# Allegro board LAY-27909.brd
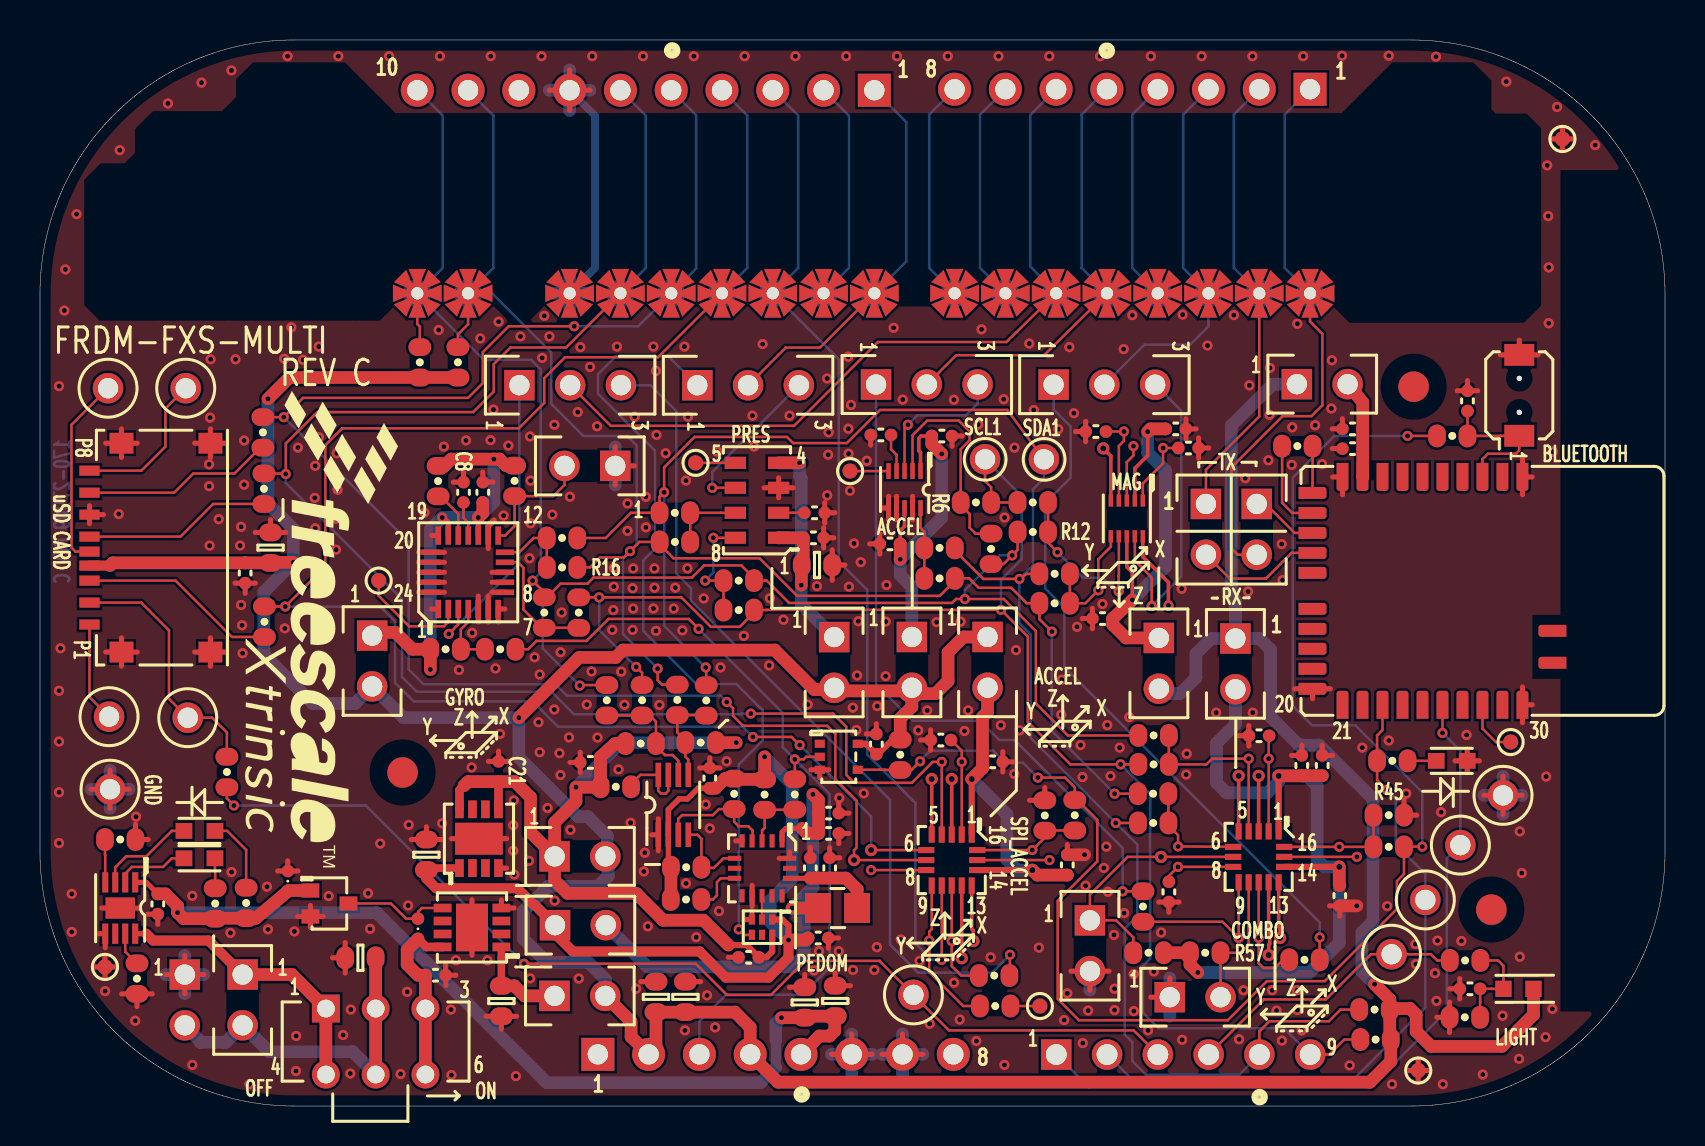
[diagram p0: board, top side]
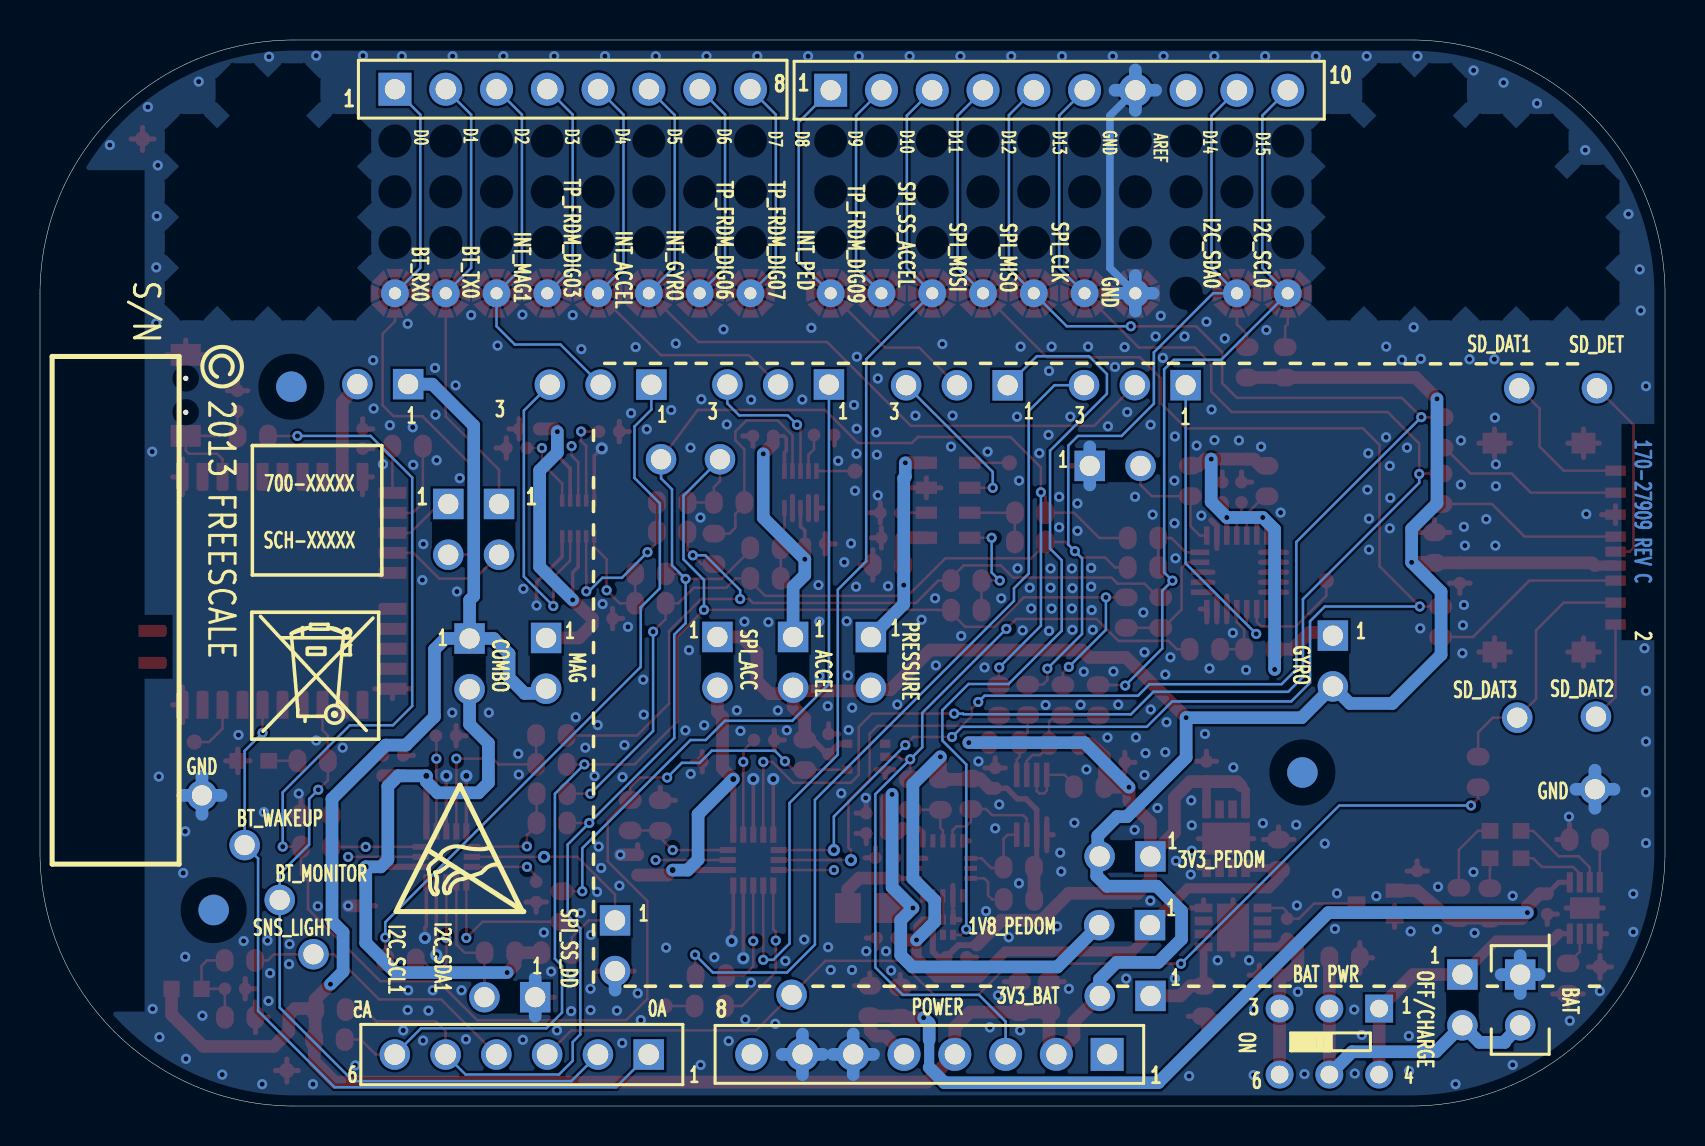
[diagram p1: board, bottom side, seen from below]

Outline 81.28 x 53.34 mm; copper layers: TOP, BOTTOM. Coordinates in mm from the lower left corner of the outline.
Outline path: 0,40.64 0,12.7 arc(3.74,3.72) 12.73,0 68.58,0 arc(77.56,3.72) 81.28,12.7 81.28,40.64 arc(77.56,49.62) 68.58,53.34 12.73,53.34 arc(3.73,49.63) 0,40.64

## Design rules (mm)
net group POW: nets P3V3
net group POWER_SPACE: nets P1V8 P1V8_MMA9553L_VDDA P1V8_PED P3V3_ACCEL P3V3_BT P3V3_COMBO P3V3_GYRO P3V3_MAG P3V3_PEDOM P3V3_PRESSURE P3V3_SPI_ACC P3V3_VBAT P3V7_BAT P4V2_BAT P4V2_BAT_OUT P5-9V_VOUT P5V_USB
nets with their own width: min track width 0.635; nets GND

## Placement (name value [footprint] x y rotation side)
C1  4.7uF  [CC0402_25]  65.65 33.88 180 top
C2  0.1UF  [CC0402_25]  56.81 33.88 0 top
C3  0.1UF  [CC0402_25]  65.65 32.89 180 top
C4  1.0UF  [CC0402_25]  45.11 33.52 0 top
C5  0.1UF  [CC0402_25]  42.06 33.58 180 top
C6  0.1UF  [CC0402_25]  52.81 33.75 180 top
C7  0.1UF  [CC0402_25]  57.44 32.92 0 top
C8  0.1UF  [CC0402_25]  21.18 30.71 90 top
C9  1.0UF  [CC0402_25]  22.15 30.71 90 top
C10  0.1UF  [CC0402_25]  38.74 29.68 0 top
C11  10uF  [CC0603_OV]  11.53 27.94 90 top
C12  0.1UF  [CC0402_25]  38.69 28.43 0 top
C13  0.1UF  [CC0402_25]  10.26 26.67 270 top
C14  10uF  [CC0603_OV]  38.86 27.07 0 top
C15  0.1UF  [CC0402_25]  42.51 28.13 180 top
C16  1.0UF  [CC0402_25]  53.15 24.39 180 top
C17  0.1UF  [CC0402_25]  45.06 18.31 180 top
C18  0.1UF  [CC0402_25]  60.97 18.53 180 top
C19  4.7uF  [CC0402_25]  63.11 17.04 90 top
C20  0.1UF  [CC0402_25]  64.14 17.04 90 top
C21  1.0UF  [CC0402_25]  22.94 16.74 90 top
C22  1.0UF  [CC0402_25]  47.65 17.22 0 top
C23  0.1UF  [CC0402_25]  27.53 17.19 180 top
C24  0.1UF  [CC0402_25]  33.5 16.41 90 top
C25  1.0UF  [CC0402_25]  39.45 14.66 0 top
C26  0.1UF  [CC0402_25]  39.45 13.64 0 top
C27  10uF  [CC0603_OV]  19.33 12.57 90 top
C28  0.1UF  [CC0402_25]  51.38 12.07 90 top
C29  0.1UF  [CC0402_25]  38.53 11.91 90 top
C30  1.0UF  [CC0402_25]  39.5 11.91 90 top
C31  0.1UF  [CC0402_25]  56.46 10.71 270 top
C32  0.1UF  [CC0402_25]  65.01 10.52 270 top
C33  0.1UF  [CC0402_25]  38.93 8.41 0 top
C34  1.0UF  [CC0402_25]  5.89 10.11 270 top
C35  10uF  [CC0603_OV]  16.03 7.42 180 top
C36  0.1UF  [CC0402_25]  35.45 7.44 180 top
C37  1.0UF  [CC0402_25]  19.78 6.55 0 top
C38  10uF  [CC0603_OV]  23.08 5.25 270 top
C39  0.1UF  [CC0402_25]  71.52 5.86 180 top
C40  2.2UF  [CC0603_OV]  30.81 5.46 90 top
C41  10uF  [CC0603_OV]  32.28 5.46 90 top
C42  10uF  [CC0603_OV]  39.78 5.26 90 top
C43  2.2UF  [CC0603_OV]  38.25 5.18 90 top
C44  1.0UF  [CC0402_25]  41.83 18.11 90 top
C46  0.1UF  [CC0402_25]  71.4 35.28 90 top
D1  BLUE  [LED_0603]  70.61 17.27 0 top
D2  LED GREEN  [LED_0603]  7.98 13.77 180 top
D3  LED ORANGE  [LED_0603]  7.98 12.4 180 top
J1  SKT_1X8  [CON_SKT1X8_TH]  63.53 50.88 90 bottom
J2  SKT_1X10  [CON_SKT1X10_TH]  41.73 50.83 90 bottom
J3  HDR TH 1X3  [HDR103]  50.7 36.09 90 top
J4  HDR TH 1X3  [HDR103]  41.82 36.1 90 top
J5  HDR TH 1X3  [HDR103]  32.88 36.06 90 top
J6  HDR TH 1X3  [HDR103]  23.98 36.07 90 top
J7  HDR 1X2 TH  [HDR102]  62.87 36.12 90 top
J8  HDR 1X2 TH  [SH_HDR102_BOTTOM]  28.77 32.03 270 top
J9  SKT_1X8  [CON_SKT1X8_TH]  27.9 2.58 270 bottom
J10  SKT_1X6  [CON_SKT1X6_TH]  50.83 2.58 270 bottom
J11  CON microSD  [CON8_SDCARD_PUSH_SM]  6.4 27.94 270 top
J12  HDR 1X2 TH  [SH_HDR102_BOTTOM]  55.96 23.42 0 top
J13  HDR 1X2 TH  [SH_HDR102_BOTTOM]  43.61 23.47 0 top
J14  HDR 1X2 TH  [SH_HDR102_BOTTOM]  39.72 23.46 0 top
J15  HDR 1X2 TH  [SH_HDR102_BOTTOM]  16.61 23.54 0 top
J16  HDR 1X2 TH  [SH_HDR102_BOTTOM]  59.79 23.39 0 top
J17  HDR 1X2 TH  [SH_HDR102_BOTTOM]  47.4 23.47 0 top
J18  HDR 1X2 TH  [SH_HDR102_BOTTOM]  25.74 12.49 90 top
J19  HDR 1X2 TH  [SH_HDR102_BOTTOM]  10.13 6.58 0 top
J20  HDR 1X2 TH  [SH_HDR102_BOTTOM]  25.76 9.05 90 top
J21  HDR 1X2 TH  [SH_HDR102_BOTTOM]  52.52 9.29 0 top
J22  HDR 1X2 TH  [HDR102]  25.73 5.51 90 top
J23  HDR 1X2 TH  [SH_HDR102_BOTTOM]  56.51 5.45 90 top
J24  HDR 1X2 TH  [HDR102]  7.24 6.58 180 bottom
J25  HDR 1X2 TH  [SH_HDR102_BOTTOM]  60.86 30.12 0 top
J26  HDR 1X2 TH  [SH_HDR102_BOTTOM]  58.32 30.12 0 top
L1  330 OHM  [IND_0805]  39.89 9.91 180 top
NOREF  -  []  59.45 10.97 90 top
NOREF#2  -  []  44.33 12.81 90 top
NOREF#3  -  []  44.6 11.03 0 top
NOREF#4  -  []  70.32 0.01 90 top
NOREF#5  -  []  -16.59 -36.7 0 top
NOREF#6  -  []  14.31 2.92 0 top
NOREF#7  -  []  10.29 35.81 270 top
NOREF#8  -  []  44.6 11.03 0 top
NOREF#9  -  []  8.69 5.03 0 top
NOREF#10  -  []  -381.97 185.27 0 top
NOREF#11  -  [unnamed#2]  68.71 35.99 0 top
NOREF#12  -  []  59.95 11.19 90 top
NOREF#13  -  []  59.45 10.97 0 top
NOREF#14  -  []  -32.92 -145.92 0 top
NOREF#15  -  []  7.24 6.58 0 top
NOREF#16  -  []  44.33 11.81 0 top
NOREF#17  -  []  62.45 10.98 0 top
NOREF#18  -  []  44.6 11.03 90 top
NOREF#19  -  []  27.17 40.56 0 top
NOREF#20  -  [unnamed#2]  18.14 16.69 0 top
NOREF#21  -  []  44.33 12.31 90 top
NOREF#22  -  []  59.95 11.19 0 top
NOREF#23  -  []  78.12 49.02 0 top
NOREF#24  -  []  59.68 11.97 0 top
NOREF#25  -  []  192.91 64.47 0 top
NOREF#26  -  []  47.1 10.82 0 top
NOREF#27  -  []  59.95 11.19 0 top
NOREF#28  -  []  17.63 46.92 0 top
NOREF#29  -  []  14.3 1.57 90 top
NOREF#30  -  []  14.31 1.42 90 top
NOREF#31  -  []  59.95 11.19 0 top
NOREF#32  -  []  44.1 10.81 90 top
NOREF#33  -  []  8.69 -3.96 90 top
NOREF#34  -  [unnamed#2]  72.59 9.83 0 top
NOREF#35  -  []  7.16 3.38 0 top
NOREF#36  -  []  14.3 1.57 0 top
NOREF#37  -  []  43.62 50.09 0 top
NOREF#38  -  []  44.1 10.81 0 top
NOREF#39  -  []  59.68 12.97 90 top
NOREF#40  -  []  -408 -339.88 0 top
NOREF#41  -  []  0 41.47 0 top
NOREF#42  -  []  44.6 11.03 0 top
NOREF#43  -  []  7.24 4.04 0 top
NOREF#44  -  []  64.74 46.67 0 top
NOREF#45  -  []  -28.19 6.65 0 top
NOREF#46  -  []  59.68 12.47 90 top
NOREF#47  -  []  55.29 -16.24 180 bottom
NOREF#48  -  []  91.82 39.52 180 bottom
NOREF#49  -  []  54.66 12.88 180 bottom
NOREF#50  -  []  54.61 5.51 180 bottom
NOREF#51  -  []  2.8 32.76 270 bottom
NOREF#52  -  [unnamed#2]  68.71 35.99 180 bottom
NOREF#53  -  [unnamed#2]  72.59 9.8 180 bottom
NOREF#54  -  [unnamed#2]  18.14 16.69 180 bottom
NOREF#55  -  []  8.16 33.42 270 bottom
NOREF#56  -  []  25.11 -7.83 180 bottom
NOREF#57  -  []  41.72 -15.38 180 bottom
Q1  NTS4001NT1G  [SC70_3]  14.48 10.13 270 top
Q2  ALS-PT19-315C/L177/TR8  [PHTRANS_1P9X1]  73.95 5.86 180 top
R1  0  [RC0603_OV]  9.35 16.71 90 top
R2  0  [RC0603_OV]  70.64 33.53 180 top
R3  0  [RC0603_OV]  11.15 33.71 270 top
R4  10K  [RC0603_OV]  19.91 31.27 270 top
R5  10K  [RC0603_OV]  23.74 31.28 270 top
R6  0  [RC0603_OV]  46.81 30.2 0 top
R7  0  [RC0603_OV]  49.66 30.2 180 top
R8  0  [RC0603_OV]  62.89 33.02 0 top
R9  0  [RC0603_OV]  11.2 30.89 270 top
R10  0  [RC0603_OV]  31.75 29.68 180 top
R11  0  [RC0603_OV]  47.57 27.88 270 top
R12  0  [RC0603_OV]  49.66 28.72 180 top
R13  0  [RC0603_OV]  26.11 28.42 0 top
R14  0  [RC0603_OV]  31.76 28.22 180 top
R16  0  [RC0603_OV]  26.11 26.95 0 top
R18  0  [RC0603_OV]  50.75 26.63 180 top
R19  0  [RC0603_OV]  50.75 25.16 180 top
R20  0  [RC0603_OV]  44.99 26.4 0 top
R21  0  [RC0603_OV]  44.99 27.93 0 top
R22  0  [RC0603_OV]  11.23 24.23 270 top
R23  0  [RC0603_OV]  34.95 24.82 0 top
R24  0  [RC0603_OV]  34.95 26.29 0 top
R25  0  [RC0603_OV]  25.22 24.69 90 top
R26  0  [RC0603_OV]  26.95 24.69 90 top
R27  10K  [RC0603_OV]  20.29 22.85 0 top
R28  0  [RC0603_OV]  23.02 22.85 0 top
R29  0  [RC0603_OV]  28.35 20.3 90 top
R30  0  [RC0603_OV]  30.12 20.3 90 top
R31  0  [RC0603_OV]  33.32 20.29 90 top
R32  0  [RC0603_OV]  31.88 20.32 90 top
R33  0  [RC0603_OV]  55.7 17.09 180 top
R34  0  [RC0603_OV]  55.7 18.54 180 top
R35  10K  [RC0603_OV]  43.03 17.58 270 top
R36  4.7K  [RC0603_OV]  30.05 18.14 0 top
R37  4.7K  [RC0603_OV]  33.05 18.19 180 top
R38  1.1K  [RC0603_OV]  67.64 17.27 0 top
R39  0  [RC0603_OV]  55.67 15.63 180 top
R40  4.7K  [RC0603_OV]  34.72 15.62 270 top
R41  0  [RC0603_OV]  37.75 15.59 270 top
R42  4.7K  [RC0603_OV]  36.24 15.58 270 top
R43  200K  [RC0603_OV]  28.8 15.97 0 top
R44  0  [RC0603_OV]  67.46 12.97 0 top
R45  10K  [RC0603_OV]  67.46 14.55 0 top
R46  0  [RC0603_OV]  51.76 14.55 270 top
R47  10K  [RC0603_OV]  50.26 14.54 90 top
R48  0  [RC0603_OV]  55.68 14.16 180 top
R49  4.7K  [RC0603_OV]  32.32 11.95 0 top
R50  0  [RC0603_OV]  4.01 13.34 0 top
R51  4.7K  [RC0603_OV]  32.31 10.34 0 top
R52  1.2K  [RC0603_OV]  10.31 10.16 90 top
R53  1K  [RC0402_25]  18.9 8.87 90 top
R54  3.3K  [RC0603_OV]  8.76 10.13 90 top
R55  10K  [RC0603_OV]  55.45 7.67 180 top
R56  1K  [RC0402_25]  12.4 11.25 90 top
R57  10K  [RC0603_OV]  58.28 7.67 0 top
R58  0  [RC0603_OV]  71.28 7.28 180 top
R59  2.7K  [RC0603_OV]  71.27 4.44 180 top
R60  22K  [RC0603_OV]  4.85 6.38 270 top
R61  10K  [RC0603_OV]  19 37.21 90 top
R62  10K  [RC0603_OV]  20.9 37.21 90 top
R63  10K  [RC0603_OV]  66.75 4.83 180 top
R64  10K  [RC0603_OV]  66.8 3.33 180 top
R65  0  [RC0603_OV]  55.17 9.98 90 top
R66  0  [RC0603_OV]  63.25 7.32 0 top
R67  0  [RC0603_OV]  47.78 5 180 top
R68  0  [RC0603_OV]  47.73 6.53 180 top
SW1  JS202011AQN  [SW6_2P5_9X3P6]  14.3 4.88 270 top
SW5  SW2_STM151XX  [SW2_4X3MM_SM]  73.99 35.56 90 top
TP1  TEST POINT WHITE  [TEST_LOOP]  45.75 40.67 0 top
TP2  TEST POINT WHITE  [TEST_LOOP]  48.29 40.67 0 top
TP3  TEST POINT WHITE  [TEST_LOOP]  50.83 40.67 0 top
TP4  TEST POINT WHITE  [TEST_LOOP]  53.37 40.67 0 top
TP5  TEST POINT WHITE  [TEST_LOOP]  55.91 40.67 0 top
TP6  TEST POINT WHITE  [TEST_LOOP]  58.45 40.67 0 top
TP7  TEST POINT WHITE  [TEST_LOOP]  60.99 40.67 0 top
TP8  TEST POINT WHITE  [TEST_LOOP]  63.53 40.67 0 top
TP9  TEST POINT WHITE  [TEST_LOOP]  18.87 40.67 0 top
TP10  TEST POINT WHITE  [TEST_LOOP]  21.41 40.67 0 top
TP11  TEST POINT WHITE  [TEST_LOOP]  26.49 40.67 0 top
TP12  TEST POINT WHITE  [TEST_LOOP]  29.03 40.67 0 top
TP13  TEST POINT WHITE  [TEST_LOOP]  31.57 40.67 0 top
TP14  TEST POINT WHITE  [TEST_LOOP]  34.11 40.67 0 top
TP15  TEST POINT WHITE  [TEST_LOOP]  36.65 40.67 0 top
TP16  TEST POINT WHITE  [TEST_LOOP]  39.19 40.67 0 top
TP17  TEST POINT WHITE  [TEST_LOOP]  41.73 40.67 0 top
TP18  -  [TPAD_030]  76.15 48.39 0 top
TP19  TEST POINT WHITE  [TEST_LOOP]  50.22 32.36 0 top
TP20  TEST POINT WHITE  [TEST_LOOP]  47.27 32.36 0 top
TP21  TEST POINT WHITE  [TEST_LOOP]  7.39 19.43 0 top
TP22  TEST POINT WHITE  [TEST_LOOP]  3.4 35.92 0 top
TP23  TEST POINT WHITE  [TEST_LOOP]  7.29 35.92 0 top
TP24  TEST POINT WHITE  [TEST_LOOP]  3.45 19.48 0 top
TP25  -  [TPAD_030]  73.56 18.21 0 top
TP26  -  [TPAD_030]  3.25 6.96 0 top
TP27  TEST POINT WHITE  [TEST_LOOP]  3.51 15.85 0 top
TP28  TEST POINT WHITE  [TEST_LOOP]  73.18 15.54 0 top
TP29  TEST POINT WHITE  [TEST_LOOP]  67.6 7.59 0 top
TP30  -  [TPAD_030]  68.94 1.78 0 top
TP31  -  [TPAD_030]  50.01 5 0 top
TP32  -  [TPAD_030]  16.94 26.29 0 top
TP33  -  [TPAD_030]  40.52 31.77 0 top
TP34  -  [TPAD_030]  32.79 32.18 0 top
TP35  TEST POINT WHITE  [TEST_LOOP]  43.69 5.56 0 top
TP36  TEST POINT WHITE  [TEST_LOOP]  69.29 10.31 0 top
TP37  TEST POINT WHITE  [TEST_LOOP]  71.04 13.06 0 top
U1  MPL3115A2  [LGA8_1P25_3X5_0P5]  35.86 30.31 180 top
U2  MAG3110  [DFN_10_0P4_2X2_A]  54.36 29.4 270 top
U3  MMA8652FC  [DFN_10_0P4_2X2]  43.24 30.85 270 top
U4  FXAS21000CQ  [QFN24_0P5_4X4_ASYM_EXP]  21.42 26.71 90 top
U5  BR-LE4.0-D2A  [BLUETOOTH_MODULE_18X12]  72.15 25.78 180 top
U6  NL17SZ06DF  [SOT353]  39.95 17.48 270 top
U7  PCA9306DCUR  [SSOP8_DCU]  31.68 15.07 0 top
U8  AP7361  [TDFN8_0P65_3X3]  21.96 13.38 90 top
U9  FXOS8700CQ  [QFN5X3_0P5_3X3]  60.95 12.47 270 top
U10  FXLS8471Q  [QFN5X3_0P5_3X3]  45.6 12.31 270 top
U11  MMA9553L  [LGA16_0P5_3X3_A]  36.12 11.89 270 top
U12  FXLP34L6X  [MICROPAK_6P]  36.12 8.95 180 top
U13  AP7361  [TDFN8_0P65_3X3]  21.61 8.93 180 top
U14  MC34673AEP  [DFN_8_0P5_2X3]  4.01 9.91 270 top

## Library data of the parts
C1-C44 C46 = CAP_NP
D1-D3 = LED
J1 J9 = CONN_HDR_8X1
J2 = CONN_HDR_10X1
J3-J6 = CONN_HDR_3X1
J7 J8 J12-J26 = CONN_HDR_2X1
J10 = CONN_HDR_6X1
J11 = CON8_SDCARD_SW
L1 = BEAD
Q1 = MOSFET_N
Q2 = PT12_PHTRANS_2P
R1-R14 R16 R18-R68 = RES
SW1 = SW_DPDT_6P
SW5 = SW2_STM151XX
TP1-TP37 = TestLoop
U1 = PPL3115A2_LGA_8P
U2 = MAG3112_DFN_10P
U3 = MMA8652_DFN10
U4 = LEON_24P
U5 = BR-LE4.0-D2A_32P
U6 = NL17SZ06
U7 = PCA9306DCUR
U8 U13 = AP7361_8P
U9 = FXOS8700CQ_QFN_16P
U10 = FXLS8471Q_16P
U11 = MMA9550_LGA_16P
U12 = FXLP34
U14 = MC34673AEP

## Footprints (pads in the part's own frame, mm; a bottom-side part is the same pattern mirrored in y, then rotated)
BLUETOOTH_MODULE_18X12
  custom 0.15x0.15 smd: 1(-2,-5.7) 2(-1,-5.7) 3(0,-5.7) 4(1,-5.7) 5(2,-5.7) 6(3,-5.7) 7(4,-5.7) 8(5,-5.7) 9(6,-5.7) 10(7,-5.7) 11(8.5,-4.9) 12(8.5,-3.9) 13(8.5,-2.9) 14(8.5,-1.9) 15(8.5,-0.9) 16(8.5,0.9) 17(8.5,1.9) 18(8.5,2.9) 19(8.5,3.9) 20(8.5,4.9) 21(7,5.7) 22(6,5.7) 23(5,5.7) 24(4,5.7) 25(3,5.7) 26(2,5.7) 27(1,5.7) 28(0,5.7) 29(-1,5.7) 30(-2,5.7) 31(-3.5,3.6) 32(-3.5,2)
CC0402_25
  round 0.635 smd: 1(-0.508,0) 2(0.508,0)
CC0603_OV
  oval 0.889x1.143 smd: 1(-0.762,0) 2(0.762,0)
CON8_SDCARD_PUSH_SM
  rect 0.508x1.016 smd: G1(0.2,-3.925) P1(3.85,-3.925) P2(2.75,-3.925) P3(1.65,-3.925) P4(0.9,-3.925) P5(-0.55,-3.925) P6(-1.65,-3.925) P7(-2.75,-3.925) P8(-3.85,-3.925)
  rect 1.041x1.194 smd: S1(5.225,-2.325) S2(5.225,2.125) S3(-5.225,2.125) S4(-5.225,-2.325)
CON_SKT1X6_TH
  rect 1.524x1.524 hole 1.041: 1(0,0)
  round 1.524 hole 1.041: 2(0,-2.54) 3(0,-5.08) 4(0,-7.62) 5(0,-10.16) 6(0,-12.7)
CON_SKT1X8_TH
  rect 1.651x1.651 hole 1.016: 1(0,0)
  round 1.651 hole 1.016: 2(0,-2.54) 3(0,-5.08) 4(0,-7.62) 5(0,-10.16) 6(0,-12.7) 7(0,-15.24) 8(0,-17.78)
CON_SKT1X10_TH
  rect 1.651x1.651 hole 1.016: 1(0,0)
  round 1.651 hole 1.016: 2(0,-2.54) 3(0,-5.08) 4(0,-7.62) 5(0,-10.16) 6(0,-12.7) 7(0,-15.24) 8(0,-17.78) 9(0,-20.32) 10(0,-22.86)
DFN_8_0P5_2X3
  rect 1.016x0.305 smd: 1(-1.285,0.75) 2(-1.285,0.25) 3(-1.285,-0.25) 4(-1.285,-0.75) 5(1.285,-0.75) 6(1.285,-0.25) 7(1.285,0.25) 8(1.285,0.75)
  rect 1.067x1.473 smd: 9(0,0)
DFN_10_0P4_2X2
  rect 0.787x0.229 smd: 1(-0.925,0.8) 2(-0.925,0.4) 3(-0.925,0) 4(-0.925,-0.4) 5(-0.925,-0.8) 6(0.925,-0.8) 7(0.925,-0.4) 8(0.925,0) 9(0.925,0.4) 10(0.925,0.8)
DFN_10_0P4_2X2_A
  rect 0.61x0.229 smd: 1(-0.895,0.8) 2(-0.895,0.4) 3(-0.895,0) 4(-0.895,-0.4) 5(-0.895,-0.8) 6(0.895,-0.8) 7(0.895,-0.4) 8(0.895,0) 9(0.895,0.4) 10(0.895,0.8)
HDR102
  rect 1.524x1.524 hole 1.016: 1(0,0)
  round 1.524 hole 1.016: 2(0,-2.54)
HDR103
  rect 1.524x1.524 hole 1.016: 1(0,0)
  round 1.524 hole 1.016: 2(0,-2.54) 3(0,-5.08)
IND_0805
  rect 1.295x1.499 smd: 1(-0.978,0) 2(0.978,0)
LED_0603
  rect 0.838x0.787 smd: A(-0.775,0) C(0.775,0)
LGA8_1P25_3X5_0P5
  rect 1.067x0.61 smd: 1(-1.083,1.875) 2(-1.083,0.625) 3(-1.083,-0.625) 4(-1.083,-1.875) 5(1.083,-1.875) 6(1.083,-0.625) 7(1.083,0.625) 8(1.083,1.875)
LGA16_0P5_3X3_A
  rect 0.66x0.254 smd: 1(-1.375,1) 2(-1.375,0.5) 3(-1.375,0) 4(-1.375,-0.5) 5(-1.375,-1) 9(1.375,-1) 10(1.375,-0.5) 11(1.375,0) 12(1.375,0.5) 13(1.375,1)
  rect 0.254x0.66 smd: 6(-0.5,-1.375) 7(0,-1.375) 8(0.5,-1.375) 14(0.5,1.375) 15(0,1.375) 16(-0.5,1.375)
MICROPAK_6P
  rect 0.305x0.508 smd: 1(-0.508,-0.381) 2(0,-0.381) 3(0.508,-0.381) 4(0.508,0.381) 5(0,0.381) 6(-0.508,0.381)
PHTRANS_1P9X1
  rect 0.813x0.813 smd: 1(-0.75,0) 2(0.75,0)
QFN5X3_0P5_3X3
  rect 0.813x0.305 smd: 1(-1.275,1) 2(-1.275,0.5) 3(-1.275,0) 4(-1.275,-0.5) 5(-1.275,-1) 9(1.275,-1) 10(1.275,-0.5) 11(1.275,0) 12(1.275,0.5) 13(1.275,1)
  rect 0.305x0.813 smd: 6(-0.5,-1.275) 7(0,-1.275) 8(0.5,-1.275) 14(0.5,1.275) 15(0,1.275) 16(-0.5,1.275)
QFN24_0P5_4X4_ASYM_EXP
  rect 0.914x0.279 smd: 1(-1.837,1.5) 2(-1.837,1) 3(-1.837,0.5) 4(-1.837,0) 5(-1.837,-0.5) 6(-1.837,-1) 7(-1.837,-1.5) 13(1.837,-1.5) 14(1.837,-1) 15(1.837,-0.5) 16(1.837,0) 17(1.837,0.5) 18(1.837,1) 19(1.837,1.5)
  rect 0.279x0.914 smd: 8(-1,-1.837) 9(-0.5,-1.837) 10(0,-1.837) 11(0.5,-1.837) 12(1,-1.837) 20(1,1.837) 21(0.5,1.837) 22(0,1.837) 23(-0.5,1.837) 24(-1,1.837)
RC0402_25
  round 0.635 smd: 1(-0.508,0) 2(0.508,0)
RC0603_OV
  oval 0.889x1.143 smd: 1(-0.762,0) 2(0.762,0)
SC70_3
  rect 0.711x0.889 smd: 1(-0.648,-0.952) 2(0.648,-0.952) 3(0,0.952)
SH_HDR102_BOTTOM
  rect 1.524x1.524 hole 1.016: 1(0,0)
  round 1.524 hole 1.016: 2(0,-2.54)
SOT353
  rect 0.406x0.508 smd: 1(-0.65,-0.95) 2(0,-0.95) 3(0.65,-0.95) 4(0.65,0.95) 5(-0.65,0.95)
SSOP8_DCU
  rect 0.279x1.219 smd: 1(-0.75,-1.499) 2(-0.25,-1.499) 3(0.25,-1.499) 4(0.75,-1.499) 5(0.75,1.499) 6(0.25,1.499) 7(-0.25,1.499) 8(-0.75,1.499)
SW2_4X3MM_SM
  round 0.254 hole 0.711 unplated: (-0.85,0) (0.85,0)
  rect 1.092x1.499 smd: 1(-2.025,0) 2(2.025,0)
SW6_2P5_9X3P6
  rect 1.397x1.397 hole 0.889: 1(0,0)
  round 1.397 hole 0.889: 2(0,2.489) 3(0,4.978) 4(3.302,0) 5(3.302,2.489) 6(3.302,4.978)
TDFN8_0P65_3X3
  rect 0.889x0.432 smd: 1(-1.471,0.975) 2(-1.471,0.325) 3(-1.471,-0.325) 4(-1.471,-0.975) 5(1.471,-0.975) 6(1.471,-0.325) 7(1.471,0.325) 8(1.471,0.975)
  rect 1.6x2.388 smd: 9(0,0)
TEST_LOOP
  custom 0.61x0.61 hole 0.889: 1(0,0)
TPAD_030
  round 0.762 smd: 1(0,0)
unnamed#2
  round 1.524 smd: (0,0)

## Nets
GND: C1.2 C2.2 C3.2 C4.2 C5.2 C6.2 C7.2 C8.2 C9.2 C10.2 C11.2 C12.2 C13.2 C14.2 C15.2 C16.2 C17.2 C18.2 C19.2 C20.2 C21.2 C22.2 C23.2 C24.2 C25.2 C26.2 C27.2 C28.2 C29.2 C30.2 C31.2 C32.2 C33.2 C34.2 C35.2 C36.2 C37.2 C38.2 C39.2 C40.2 C41.2 C42.2 C43.2 C44.2 C46.2 D1.C(CATHODE) J2.7 J8.1 J9.6 J9.7 J11.P6(VSS) J11.S1 J11.S2 J11.S3 J11.S4 J21.2 J23.1 J24.1 Q1.2(SOURCE) R45.2 R47.2 R50.2 R56.2 R59.2 R60.2 SW5.2(SW2) TP11.1(PIN1) TP18.1(PIN1) TP26.1(PIN1) TP27.1(PIN1) TP28.1(PIN1) TP30.1(PIN1) U1.3(GND) U2.5(GND1) U2.10(GND2) U3.6(GND1) U3.7(GND2) U3.9(GND3) U4.1(VSS1) U4.5(VSS2) U4.6(RSVD1) U4.7(RSVD2) U4.8(RSVD3) U4.9(RSVD4) U4.10(RSVD5) U4.14(VSS3) U4.19(VSS4) U4.20(RSVD6) U4.21(RSVD7) U4.22(RSVD8) U4.23(RSVD9) U4.24(RSVD10) U5.1(GND1) U5.10(GND2) U5.20(GND3) U5.30(GND4) U6.3(GND) U7.1(GND) U8.4(GND) U8.9(EPAD) U9.3(RSVD1) U9.5(GND1) U9.12(GND2) U9.13(RSVD2) U10.3(RSRV_3) U10.5(GND1) U10.12(GND2) U10.13(RSRV_13) U11.5(VSS1) U11.10(VSS2) U11.16(VSSA) U12.3(GND) U13.4(GND) U13.9(EPAD) U14.5(GND) U14.9(EPAD)
P1V8: C24.1 C27.1 C33.1 J20.1 R40.1 R42.1 R49.1 R51.1 U7.2(VREF1) U8.1(OUT) U12.1(VCC1)
P1V8_MMA9553L_VDDA: C29.1 C30.1 L1.1 U11.14(VDDA)
P1V8_PED: C25.1 C26.1 J20.2 L1.2 U11.1(VDD)
P3V3: C11.1 C13.1 C40.1 C41.1 C44.1 J7.1 J9.2 J9.4 J11.P4(VDD) J12.2 J13.2 J14.2 J15.2 J16.1 J17.1 J18.2 J22.2 Q2.1(COLLECTOR) R35.1 R61.1 R62.1 R63.1 R64.1 U6.5(VCC)
P3V3_ACCEL: C4.1 C15.1 J13.1 U3.1(VDD) U3.8(VDDIO)
P3V3_BT: C1.1 C3.1 J7.2 U5.9(VDD)
P3V3_COMBO: C19.1 C20.1 C32.1 J16.2 R55.1 R57.1 U9.1(VDDIO) U9.14(VDD)
P3V3_GYRO: C9.1 J15.1 R4.1 R5.1 R27.1 U4.15(VDD) U4.18(VDDIO)
P3V3_MAG: C2.1 C16.1 J12.1 U2.2(VDD) U2.8(VDDIO)
P3V3_PEDOM: C21.1 C23.1 C36.1 J18.1 R36.1 R37.1 R43.1 U8.5(EN) U8.8(IN) U12.6(VCC)
P3V3_PRESSURE: C12.1 C14.1 J14.1 U1.1(VDD) U1.4(VDDIO)
P3V3_SPI_ACC: C22.1 C28.1 J17.2 U10.1(VDDIO) U10.14(VDD)
P3V3_VBAT: C38.1 J22.1 U13.1(OUT)
P3V7_BAT: C37.1 R53.1 SW1.3 SW1.6 U13.8(IN)
P4V2_BAT: C35.1 J19.2 J24.2 SW1.2 SW1.5
P4V2_BAT_OUT: J19.1 SW1.1 SW1.4 U14.8(BAT)
P5V_USB: C34.1 C42.1 C43.1 J9.5 Q1.1(GATE) R52.1 R54.1 R56.1 U14.1(VIN)
VBAT_EN: Q1.3(DRAIN) R53.2 U13.5(EN)
ACC_BYP: C17.1 U10.2(BYP)
BAT_CHG_B: D2.C(CATHODE) U14.3(C\H\G\)
BAT_CHG_EN: R50.1 U14.4(E\N\)
BAT_CHG_LED_B: D2.A(ANODE) R52.2
BAT_ISET: R60.1 U14.7(ISET)
BAT_PPR_B: D3.C(CATHODE) U14.2(P\P\R\)
BAT_PPR_LED_B: D3.A(ANODE) R54.2
BT_CTS: R8.2 U5.11(UART_CTS)
BT_MONITOR: J10.2 R38.1 TP36.1(PIN1) U5.23(PIO_2)
BT_RTS: R8.1 U5.12(UART_RTS)
BT_RX: J26.2 U5.14(UART_RX)
BT_RX0: J1.1 J25.2 TP8.1(PIN1)
BT_TX: J25.1 U5.13(UART_TX)
BT_TX0: J1.2 J26.1 TP7.1(PIN1)
BT_WAKEUP: J10.1 TP37.1(PIN1) U5.26(PIO_3)
BTMON_LED: D1.A(ANODE) R38.2
BYP_ACC: C5.1 U3.4(BYP)
BYP_FXOS8700CQ: C18.1 U9.2(BYP)
CAP_A_MAG: C7.1 U2.1(CAP_A)
CAP_MPL3115A2: C10.1 U1.2(CAP)
CAP_R_MAG: C6.1 U2.4(CAP_R)
CRST_FXOS8700CQ: C31.1 U9.8(CRST)
EN_MMA9553L: R43.2 U7.7(VREF2) U7.8(EN)
FACTORY_RSVD: TP25.1(PIN1) U5.28(PIO_4)
I2C_SCL0: J2.10 R11.2 R12.2 R24.2 R25.2 R29.2 R34.2 R61.2 TP9.1(PIN1)
I2C_SCL1: J10.6 R6.2 R7.2 R23.2 R26.2 R30.2 R33.2 R64.2 TP20.1(PIN1)
I2C_SCL_FXAS21000CQ: R25.1 R26.1 U4.11(SCL/SCLK)
I2C_SCL_FXOS8700CQ: R33.1 R34.1 U9.4(SCL/SCLK)
I2C_SCL_MAG3110: R7.1 R12.1 U2.7(SCL)
I2C_SCL_MMA8652FC: R6.1 R11.1 U3.2(SCL)
I2C_SCL_MMA9553_LV: R40.2 U7.3(SCL1) U11.4(SCL0/RGPIO0/SCLK)
I2C_SCL_MMA9553L: R29.1 R30.1 R36.2 U7.6(SCL2)
I2C_SCL_MPL3115A2: R23.1 R24.1 U1.8(SCL)
I2C_SDA0: J2.9 R14.2 R16.2 R19.2 R20.2 R32.2 R39.2 R62.2 TP10.1(PIN1)
I2C_SDA1: J10.5 R10.2 R13.2 R18.2 R21.2 R31.2 R48.2 R63.2 TP19.1(PIN1)
I2C_SDA_FXAS21000CQ: R13.1 R16.1 U4.12(SDA/MOSI)
I2C_SDA_FXOS8700CQ: R39.1 R48.1 U9.6(SDA/MOSI)
I2C_SDA_MAG3110: R18.1 R19.1 U2.6(SDA)
I2C_SDA_MMA8652FC: R20.1 R21.1 U3.10(SDA)
I2C_SDA_MMA9553_LV: R49.2 U7.4(SDA1) U11.6(SDA0/RGPIO1/SDI)
I2C_SDA_MMA9553L: R31.1 R32.1 R37.2 U7.5(SDA2)
I2C_SDA_MPL3115A2: R10.1 R14.1 U1.7(SDA)
I2CSEL_FXAS21000CQ: R4.2 U4.17(I2C/S\P\I\)
INT1_ACC: R68.2 U10.11(INT1)
INT1_ACCEL: J4.3 U3.3(INT1)
INT1_COMBO: J3.1 R66.2
INT1_COMBO_R: R66.1 U9.11(INT1)
INT1_GYRO: J6.1 U4.3(INT1)
INT1_PRESSURE: J5.3 U1.6(INT1)
INT1_SPI_ACCEL: J6.3 R68.1
INT2_ACC: R67.2 U10.9(INT2)
INT2_ACCEL: TP33.1(PIN1) U3.5(INT2)
INT2_COMBO: J4.1 R65.2
INT2_COMBO_R: R65.1 U9.9(INT2)
INT2_GYRO: TP32.1(PIN1) U4.2(INT2)
INT2_PRESSURE: TP34.1(PIN1) U1.5(INT2)
INT2_SPI_ACCEL: R67.1 TP31.1(PIN1)
INT_ACCEL: J1.5 J4.2 TP4.1(PIN1)
INT_GYRO: J1.6 J6.2 TP3.1(PIN1)
INT_MAG: J1.3 J3.2 TP6.1(PIN1)
INT_MAG3110: J3.3 U2.9(INT1)
INT_MMA9553L_LV: U11.11(RGPIO5/PDB_A/INT_O) U12.2(A)
INT_PED: J2.1 J5.2 TP17.1(PIN1)
INT_PEDOMETER: J5.1 U12.4(Y)
LSENSE_EMITTER: C39.1 Q2.2(EMITTER) R58.1 R59.1
NC_FRDM_AREF: J2.8
P5-9V_VOUT: J9.8
RGPIO3_MMA9553L: R51.2 U11.8(RGPIO3/SDA1/S\S\)
RST_ACCEL: R46.2 R47.1 U10.16(RST)
RST_BT: C46.1 R2.1 SW5.1(SW1) U5.3(R\E\S\E\T\)
RST_FXAS21000CQ: R27.2 R28.1 U4.4(R\S\T\)
RST_FXOS8700CQ: R44.1 R45.1 U9.16(RST)
RST_MMA9553L: R41.2 R42.2 U11.3(R\E\S\E\T\)
RST_TGTMCU: R2.2 R35.2 R44.2 R46.1 U6.4(OUT)
RST_TGTMCU_B: J9.3 R28.2 R41.1 U6.2(IN)
SA0_FXOS8700CQ: J23.2 R57.2 U9.10(SA1/C\S\)
SA1_FXOS8700CQ: J21.1 R55.2 U9.7(SA0/MISO)
SA_GYRO: J8.2 R5.2 U4.13(SA0/MISO)
SD_CARD_DETECT: J11.G1(SWITCH) TP22.1(PIN1)
SD_CLK: J11.P5(CLK) R9.2
SD_CMD: J11.P3(CMD) R22.2
SD_DAT0: J11.P7(DAT0) R3.2
SD_DAT1: J11.P8(DAT1) TP23.1(PIN1)
SD_DAT2: J11.P1(DAT2) TP24.1(PIN1)
SD_DAT3: J11.P2(CD/DAT3) R1.2 TP21.1(PIN1)
SNS_LIGHT: J10.4 R58.2 TP29.1(PIN1)
SPI_CLK: J2.6 R9.1 TP12.1(PIN1) U10.4(SCL/SCLK)
SPI_MISO: J2.5 R3.1 TP13.1(PIN1) U10.7(SA0/MISO)
SPI_MOSI: J2.4 R22.1 TP14.1(PIN1) U10.6(SDA/MOSI)
SPI_SS_SD: J10.3 R1.1 TP35.1(PIN1)
SPI_SS_SPI_ACCEL: J2.3 TP15.1(PIN1) U10.10(SA1/C\S\)
TP_FRDM_DIG03: J1.4 TP5.1(PIN1)
TP_FRDM_DIG06: J1.7 TP2.1(PIN1)
TP_FRDM_DIG07: J1.8 TP1.1(PIN1)
TP_FRDM_DIG09: J2.2 TP16.1(PIN1)
VREGD_FXAS21000CQ: C8.1 U4.16(VREGD)

Pads without a net: J9 1; U2 3; U5 2 4 5 6 7 8 15 16 17 18 19 21 22 24 25 27 29 31 32; U6 1; U8 2 3 6 7; U9 15; U10 8 15; U11 2 7 9 12 13 15; U12 5; U13 2 3 6 7; U14 6

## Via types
v1: diameter 0.508, hole 0.254, TOP to BOTTOM, 457 vias
v2: diameter 0.61, hole 0.305, TOP to BOTTOM, 16 vias

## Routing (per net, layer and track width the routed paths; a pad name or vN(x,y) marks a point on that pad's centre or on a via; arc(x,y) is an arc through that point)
GND: length 245.9
  TOP w0.178: U9.12 61.46,8.91 61.51,8.85 61.51,8.12 61.46,8.07 v2(61.46,7.55) ; U9.13 61.95,9 62.03,8.93 v2(62.03,8.41) ; U10.12 v2(46.1,7.39) ; U10.5 v2(44.6,16.36) ; v2(53.18,32.9) 53.56,32.53 53.56,32.32 53.56,30.82 U2.5 ; U10.3 v2(45.6,16.36) ; U2.10 55.16,27.48 56.44,26.2 v1(56.44,25.04) ; v2(46.69,8.25) 46.69,8.78 46.6,8.86 U10.13 ; U9.5 v2(59.95,16.52) ; U9.3 v2(60.95,16.52)
  TOP w0.254: U6.3 39.45,16.82 ; U6.3 38.56,16.82 ; U6.3 39,16.43 ; 39.43,7.9 C33.2 39.94,8.41 ; J8.1 28.77,32.98 ; J8.1 28.77,31.08 ; J8.1 29.73,32.03 ; C11.2 12.29,28.7 ; C11.2 11.53,29.34 ; C11.2 10.77,28.7 ; 35.61,9.77 U12.3 35.26,9.33 ; 72.22,15.54 TP28.1 ; TP28.1 74.13,15.54 ; TP28.1 73.18,16.5 ; TP28.1 73.18,14.59 ; 23.34,13.38 U8.9 20.57,13.38 ; C31.2 56.97,10.21 ; C31.2 55.96,10.21 ; C31.2 56.46,9.7 ; 75.58,48.39 TP18.1 ; TP18.1 76.72,48.39 ; TP18.1 76.15,48.96 ; TP18.1 76.15,47.81 ; R59.2 70.51,5.2 ; R59.2 70.51,3.68 ; R59.2 69.87,4.44 ; C12.2 39.19,28.94 ; C12.2 39.7,28.43 ; C12.2 39.19,27.92 ; 40.46,13.64 C26.2 39.95,13.13 ; J24.1 7.24,7.53 ; J24.1 6.29,6.58 ; J24.1 7.24,5.62 ; J24.1 8.2,6.58 ; C29.2 38.53,12.93 ; C15.2 42.01,28.64 ; C15.2 41.5,28.13 ; C15.2 42.01,27.62 ; J9.7 43.14,3.6 ; J9.7 44.16,2.58 ; J9.7 42.13,2.58 ; C37.2 20.8,6.55 ; C37.2 20.29,7.05 ; C37.2 20.29,6.04 ; 20.68,31.22 C8.2 21.18,31.73 ; J11.P6 2.48,30.03 ; J11.P6 3.17,29.59 ; J11.P6 2.48,29.14 ; C7.2 57.95,33.43 ; C7.2 57.95,32.41 ; C7.2 58.46,32.92 ; TP26.1 3.25,7.53 ; TP26.1 3.25,6.39 ; TP26.1 2.68,6.96 ; TP26.1 3.82,6.96 ; 30.93,12.77 U7.1 ; U7.1 30.93,14.37 ; U7.1 30.6,13.57 ; C27.2 20.09,13.34 ; C27.2 19.33,13.97 ; C27.2 18.57,13.34 ; C6.2 52.3,34.25 ; C6.2 51.79,33.75 ; C6.2 52.3,33.24 ; C41.2 33.05,6.22 ; 21.61,10.32 U13.9 21.61,7.55 ; 48.16,16.71 C22.2 ; C22.2 48.67,17.22 ; C22.2 48.16,17.73 ; 70.51,5.86 C39.2 ; C39.2 71.02,5.36 ; C39.2 71.02,6.37 ; 4.09,5.61 R60.2 ; R60.2 5.61,5.61 ; R60.2 4.85,4.98 ; 13.53,8.94 Q1.2 ; Q1.2 13.53,10.03 ; Q1.2 14.16,9.49 ; Q1.2 12.89,9.49 ; 10.26,25.65 C13.2 ; C13.2 10.77,26.16 ; C13.2 9.75,26.16 ; R56.2 12.4,12.27 ; R56.2 12.9,11.76 ; R56.2 11.89,11.76 ; 59.96,18.53 C18.2 ; C18.2 60.46,19.04 ; C18.2 60.46,18.02 ; 42.84,30.51 U3.7 42.84,29.34 ; J9.6 40.6,3.6 ; J9.6 41.62,2.58 ; J9.6 39.59,2.58 ; D1.C 72,17.27 ; D1.C 71.39,16.69 ; D1.C 71.39,17.86 ; D1.C 70.78,17.27 ; C14.2 39.63,27.83 ; C14.2 40.26,27.07 ; C14.2 39.63,26.31 ; 30.05,6.22 C40.2 ; 41.33,18.62 C44.2 41.83,19.13 ; 39.95,15.16 C25.2 40.46,14.66 ; U8.4 23.34,11.9 ; 23.71,9.91 U13.4 23.08,10.32 ; 8.53,22 J11.S2 ; J11.S2 8.53,23.43 ; J11.S2 7.74,22.71 ; J11.S2 9.31,22.71 ; C28.2 51.38,13.08 ; 62.76,20.88 U5.20 ; U5.20 64.54,20.88 ; U5.20 63.65,20.39 ; 62.6,17.54 C19.2 63.11,18.05 ; 55.56,5.45 J23.1 56.51,6.4 ; J2.7 26.49,51.84 ; J2.7 25.48,50.83 ; J2.7 27.51,50.83 ; J2.7 26.49,49.81 ; 5.89,9.09 C34.2 5.38,9.6 ; U5.30 74.15,20.97 ; U5.30 74.15,19.18 ; U5.30 74.64,20.08 ; 22.42,24.22 U4.6 22.42,25.52 ; J11.S1 4.86,22.71 ; J11.S1 4.08,22 ; J11.S1 4.08,23.43 ; J11.S1 3.29,22.71 ; 32.99,16.92 C24.2 ; C24.2 33.5,17.42 ; C24.2 34.01,16.92 ; 35.62,11.04 U11.10 35.62,10 ; 44.04,18.31 C17.2 ; C17.2 44.55,17.8 ; C17.2 44.55,18.82 ; 22.43,17.25 C21.2 ; C21.2 23.44,17.25 ; C21.2 22.94,17.76 ; U5.1 74.64,31.48 ; U5.1 74.15,30.58 ; U5.1 74.15,32.37 ; 34.43,7.44 C36.2 ; SW5.2 74.93,37.58 ; SW5.2 73.05,37.58 ; SW5.2 73.99,38.32 ; 42.44,29.34 U3.6 ; U3.6 42.44,30.51 ; U3.6 42.14,29.92 ; 21.92,24.22 U4.5 21.92,25.52 ; 20.23,27.71 U4.20 18.93,27.71 ; 49.5,15.3 R47.2 50.26,15.93 ; 3.09,9.91 U14.9 4.94,9.91 ; 26.51,17.19 C23.2 ; C23.2 27.02,16.68 ; C23.2 27.02,17.7 ; 14.63,7.42 C35.2 ; C35.2 15.27,8.18 ; C35.2 15.27,6.65 ; 22.92,24.22 U4.7 23.25,24.87 ; C16.2 52.64,24.9 ; C16.2 52.64,23.88 ; C16.2 52.13,24.39 ; 2.55,15.85 TP27.1 ; TP27.1 3.51,16.8 ; TP27.1 3.51,14.9 ; TP27.1 4.46,15.85 ; 68.94,1.21 TP30.1 ; TP30.1 68.94,2.35 ; TP30.1 69.51,1.78 ; TP30.1 68.36,1.78 ; C2.2 57.32,34.39 ; C2.2 57.83,33.88 ; C2.2 57.32,33.37 ; 64.5,10.02 C32.2 65.01,9.51 ; 18.93,27.21 U4.21 20.23,27.21 ; 36.95,30.44 U1.3 ; U1.3 37.67,30.93 ; U1.3 36.95,31.43 ; U1.3 36.22,30.93 ; 51.56,6.75 J21.2 ; J21.2 53.47,6.75 ; J21.2 52.52,5.8 ; 18.93,25.71 U4.24 20.23,25.71 ; 39.25,29.17 C10.2 ; C10.2 39.76,29.68 ; C10.2 39.25,30.19 ; 23.08,3.85 C38.2 ; C38.2 23.84,4.49 ; C38.2 22.32,4.49 ; 39.78,6.66 C42.2 40.54,6.02 ; 64.66,31.48 U5.10 65.15,30.58 ; 46.13,33.52 C4.2 45.62,33.01 ; J11.S3 9.31,33.17 ; J11.S3 8.53,33.88 ; J11.S3 7.74,33.17 ; J11.S3 8.53,32.45 ; J11.S4 4.08,33.88 ; J11.S4 4.86,33.17 ; J11.S4 3.29,33.17 ; J11.S4 4.08,32.45 ; 4.78,14.1 R50.2 5.41,13.34 ; 40.01,12.42 C30.2 39.5,12.93 ; 68.86,14.55 R45.2 68.22,15.32 ; 22.15,31.73 C9.2 22.66,31.22 ; 22.61,26.71 U4.10 ; 3.26,7.92 U14.5 2.92,8.62 ; 38.25,6.58 C43.2 37.49,5.94 ; 36.97,12.39 U11.16 37.49,12.71 ; 64.14,18.05 C20.2 64.64,17.54 ; C46.2 71.91,35.79 ; C46.2 70.89,35.79 ; C46.2 71.4,36.3 ; 19.59,28.54 U4.19 ; 41.55,33.07 C5.2 ; 64.64,32.89 C3.2 ; 20.23,26.21 U4.23 18.93,26.21 ; 64.63,33.88 C1.2 65.14,34.39 ; 22.42,27.89 U4.14 ; 19.59,24.87 U4.1 ; 43.64,29.34 U3.9 43.64,30.51 ; 20.23,26.71 U4.22 18.93,26.71 ; 34.8,13.27 U11.5 ; 22.61,25.71 U4.8 ; 22.61,26.21 U4.9
  TOP w0.279: 22.71,29.31 22.42,29.02 U4.14
  TOP w0.635: C32.2 v1(65.86,10.02) ; C28.2 v1(52.25,12.57)
  BOTTOM w0.381: J2.7 27.76,49.56 27.76,41.94 TP11.1
  BOTTOM w0.635: 28.77,32.98 J8.1 28.77,31.08 ; 56.51,6.4 J23.1 56.51,4.49 ; 26.49,49.81 J2.7 ; J2.7 27.51,50.83 ; J2.7 26.49,51.84 ; J2.7 25.48,50.83 ; J9.7 43.14,3.6 ; J9.7 44.16,2.58 ; J9.7 42.13,2.58 ; J9.7 43.14,1.57 ; 2.55,15.85 TP27.1 ; TP27.1 4.46,15.85 ; TP27.1 3.51,14.9 ; TP27.1 3.51,16.8 ; 52.52,5.8 J21.2 ; 40.6,1.57 J9.6 ; J9.6 40.6,3.6 ; J9.6 41.62,2.58 ; J9.6 39.59,2.58 ; TP28.1 73.18,16.5 ; TP28.1 72.22,15.54 ; TP28.1 73.18,14.59 ; TP28.1 74.13,15.54 ; 7.24,5.62 J24.1 ; J24.1 8.2,6.58 ; J24.1 6.29,6.58 ; J24.1 7.24,7.53 ; 26.49,39.78 TP11.1 ; TP11.1 25.6,40.67 ; TP11.1 27.38,40.67 ; TP11.1 26.49,41.55
  vias: v1(0.95,36.02) v1(0.95,20.78) v1(0.95,18.24) v1(0.95,15.7) v1(0.95,13.16) v1(1.03,22.9) v1(1.27,41.86) v1(1.22,39.8) v1(1.59,10.62) v1(1.59,8.71) v1(1.83,44.63) v1(3.26,5.75) v1(3.99,47.83) v1(3.94,29.62) v1(4.76,4.27) v1(4.8,14.48) v1(6.4,50.16) v1(7.62,10.52) v1(7.62,2.06) v1(8.08,51.21) v1(8.46,32.11) v1(8.46,31.01) v1(8.48,28.04) v1(8.53,37.36) v1(8.51,34.44) v1(8.94,29.36) v1(9.58,51.82) v1(9.58,11.71) v1(9.53,8.66) v1(9.78,37.36) v1(10.06,28.98) v1(10.01,28.04) v1(10.06,25.07) v1(10.11,24.05) v1(10.13,22.66) v1(10.21,33.3) v1(10.21,31.09) v1(10.48,1.09) v1(11.35,10.97) v1(11.4,8.84) v1(12.22,37.39) v1(12.24,23.9) v1(12.38,52.53) v1(12.57,38.96) v1(12.73,8.74) v1(12.81,3.51) v1(12.8,1.75) v1(12.9,32.94) v1(13.16,37.34) v1(13.77,32.03) v1(13.74,30.43) v1(13.77,28.91) v1(13.94,38) v1(13.95,33.46) v1(14.44,10.5) v1(14.84,32.66) v1(14.88,30.84) v1(14.81,29.39) v1(14.81,27.84) v1(14.92,52.53) v1(15.16,3.56) v1(15.54,4.83) v1(15.52,1.63) v1(16.41,10.64) v1(16.51,8.86) v1(17.02,13.13) v1(17.46,52.53) v1(18.03,1.6) v1(18.36,5.71) v1(18.44,14.07) v1(18.41,10.03) v1(19.23,29.69) v1(19.94,38.83) v1(20,52.53) v1(20.12,14.15) v1(20.2,32.99) v1(20.55,4.82) v1(20.58,1.55) v1(20.8,7.29) v1(20.95,21.82) v1(21.31,33.3) v1(21.59,16.94) v1(21.62,23.67) v1(22.02,38.4) v1(22.38,7.29) v1(22.54,52.53) v1(22.54,33.32) v1(22.68,34.85) v1(22.78,21.89) v1(22.94,39.24) v1(23.01,18.62) v1(23.19,29.54) v1(23.43,33.04) v1(23.67,14.05) v1(23.67,12.78) v1(23.7,15.29) v1(23.72,11.58) v1(23.8,1.5) v1(24.03,38.5) v1(24.49,27.41) v1(24.46,12.27) v1(24.51,33.5) v1(24.54,31.29) v1(24.54,29.16) v1(24.51,6.39) v1(24.74,22.45) v1(24.93,19.2) v1(25.08,52.53) v1(24.99,21.59) v1(24.99,17.7) v1(25.12,37.43) v1(25.22,39.54) v1(25.39,14.91) v1(25.48,38.5) v1(25.63,29.59) v1(25.73,34.09) v1(25.73,19.84) v1(25.74,10.27) v1(25.98,17.65) v1(26.09,24.69) v1(26.04,22.71) v1(26.04,16.56) v1(26.46,18.44) v1(26.51,30.49) v1(26.53,13.82) v1(26.9,34.72) v1(26.95,6.38) v1(27.03,37.97) v1(27.35,20.09) v1(27.51,36.98) v1(27.59,21.74) v1(27.62,52.53) v1(27.86,34.01) v1(27.89,18.44) v1(28.68,24.82) v1(28.63,23.83) v1(28.7,26.92) v1(28.7,25.98) v1(28.86,38) v1(28.94,16.84) v1(29.07,21.73) v1(29.23,20.08) v1(29.39,30.15) v1(29.39,28.78) v1(29.54,14.17) v1(29.67,26.9) v1(29.64,25.91) v1(29.67,24.89) v1(29.64,23.83) v1(29.74,34.49) v1(29.82,5.87) v1(30.16,52.53) v1(30.25,12.67) v1(30.2,11.73) v1(30.3,30.48) v1(30.3,28.96) v1(30.4,8.99) v1(30.68,38) v1(30.68,24.89) v1(30.73,26.9) v1(30.73,25.93) v1(30.81,36.78) v1(30.84,33.58) v1(30.81,23.77) v1(30.98,20.07) v1(31.29,32.66) v1(31.78,25.93) v1(31.7,24.89) v1(32.13,23.8) v1(32.23,38) v1(32.26,3.78) v1(32.31,31.29) v1(32.38,26.9) v1(32.31,11.14) v1(32.41,34.49) v1(32.7,52.53) v1(32.83,8.45) v1(33.2,25.4) v1(33.3,15.09) v1(33.36,5.54) v1(33.5,13.89) v1(33.77,3.94) v1(33.88,32.74) v1(33.96,9.75) v1(34.04,21.95) v1(34.34,17.25) v1(35.24,52.53) v1(35.2,23.52) v1(35.64,34.54) v1(35.71,32.99) v1(36.14,38.13) v1(36.47,22.05) v1(36.51,25.41) v1(37.19,24.33) v1(37.49,34.54) v1(37.78,52.53) v1(38.4,20.09) v1(38.71,6.78) v1(38.86,26.01) v1(38.96,7.75) v1(39.37,36.4) v1(39.37,30.55) v1(39.45,33.71) v1(39.42,32.59) v1(39.98,15.42) v1(39.95,7.75) v1(40.32,52.53) v1(40.42,37.49) v1(40.43,33.89) v1(40.44,32.64) v1(40.46,25.98) v1(40.57,35.08) v1(40.51,30.78) v1(40.66,19.93) v1(40.67,6.81) v1(40.71,28.15) v1(40.87,21.54) v1(40.84,18.81) v1(40.93,24.26) v1(41.05,27.21) v1(41.2,15.64) v1(41.36,32.28) v1(41.73,6.81) v1(41.88,20.01) v1(41.86,7.95) v1(42.34,26.07) v1(42.3,24.24) v1(42.3,21.51) v1(42.7,38.94) v1(42.86,52.53) v1(43.05,8.33) v1(43.15,35.35) v1(43.93,18.8) v1(44,7.26) v1(44.37,19.79) v1(44.5,4.11) v1(44.85,24.21) v1(45.4,52.53) v1(45.71,35.34) v1(45.72,6.17) v1(46.04,24.24) v1(46,4.33) v1(46.24,18.77) v1(46.42,19.8) v1(46.84,3.25) v1(46.93,34.1) v1(47.09,38.86) v1(47.55,7.44) v1(47.94,52.53) v1(48.06,19.05) v1(48.2,35.36) v1(48.25,29.44) v1(48.24,2.06) v1(48.74,32.94) v1(48.73,16.62) v1(48.82,22.81) v1(49,18.8) v1(49.48,38.15) v1(49.71,34.82) v1(49.96,7.92) v1(50.48,52.53) v1(50.93,33.86) v1(51.08,19.58) v1(51.11,21.33) v1(51.23,4.3) v1(51.38,5.64) v1(51.49,37.97) v1(51.72,34.67) v1(51.87,23.98) v1(52.04,18.06) v1(52.15,16.46) v1(52.16,3.15) v1(52.3,11.02) v1(52.43,4.78) v1(53.02,52.53) v1(53.14,25.12) v1(53.21,11.91) v1(53.38,19.06) v1(53.34,12.98) v1(53.42,10.72) v1(53.54,16.51) v1(53.72,8.56) v1(53.75,5.87) v1(53.74,4.8) v1(54,17.93) v1(54.2,37.87) v1(54.23,9.65) v1(54.49,19.45) v1(54.64,39.57) v1(54.71,6.6) v1(54.71,4.75) v1(55.42,3.78) v1(55.56,52.53) v1(55.71,6.73) v1(56.08,8.68) v1(57.15,39.6) v1(57.1,25.88) v1(57.13,3.31) v1(57.36,17.63) v1(57.33,16.58) v1(58.1,52.53) v1(58.39,38.05) v1(58.83,19.68) v1(59.72,39.57) v1(59.97,3.34) v1(60.29,31.41) v1(60.2,5.79) v1(60.49,36.06) v1(60.43,25.74) v1(60.64,52.53) v1(60.66,19.68) v1(61.44,32.31) v1(61.52,36.93) v1(61.5,34.59) v1(61.63,5.79) v1(61.85,4.78) v1(62.11,28.12) v1(62.15,26.31) v1(62.12,3.28) v1(62.64,33.96) v1(62.61,32.08) v1(62.89,39.14) v1(62.87,5.79) v1(62.89,4.8) v1(63.18,52.53) v1(63.11,3.78) v1(63.78,34.06) v1(64.13,32.11) v1(64.59,34.9) v1(64.62,37.31) v1(65.13,52.55) v1(65.51,2.03) v1(66.14,17.93) v1(67.38,10) v1(67.46,52.55) v1(67.46,18.29) v1(67.63,1.09) v1(68.34,15.63) v1(68.8,8.1) v1(68.82,7.1) v1(69.77,6.65) v1(69.82,52.5) v1(69.85,5.26) v1(69.9,8.28) v1(70.08,14.71) v1(70.17,1.09) v1(71.09,8.25) v1(71.35,18.57) v1(72.17,1.57) v1(73.16,4.52) v1(73.34,51.26) v1(73.98,2.36) v1(74.02,13.74) v1(74.02,7.47) v1(74.12,11.66) v1(75.39,47.07) v1(75.34,16.48) v1(75.31,3.45) v1(75.44,44.53) v1(75.46,41.96) v1(75.46,39.17) v1(75.67,32.74) v1(75.65,4.86) v1(75.88,49.99) v1(77.79,48.08)
P1V8: length 48.4
  TOP w0.254: R49.1 31.43,12.08 U7.2
  TOP w0.279: C24.1 32.92,15.9 32.38,15.37 31.97,15.37 31.43,14.83 U7.2
  TOP w0.305: U12.1 37.13,9.33 37.44,9.02 v1(37.44,8.31)
  TOP w0.381: C27.1 19.42,11.9 U8.1
  TOP w0.508: v1(37.44,8.31) 37.44,7.43 36.44,6.43 34.3,6.43 32.99,7.73 26.65,7.73 25.76,8.62 J20.1 24.75,10.06 24.7,10.06 23.87,10.9 19.81,10.9 19.33,11.38 C27.1
  TOP w0.635: C24.1 33.78,15.9 34.26,16.38 R40.1 34.63,16.34 R42.1 v1(36.24,17.48) ; R51.1 31.56,10.34 R49.1 ; v1(37.44,8.31) 38.32,8.31 C33.1
  BOTTOM w0.635: v1(36.24,17.48) 37.62,16.1 37.62,11.38 36.53,10.29 36.53,9.22 v1(37.44,8.31)
P1V8_MMA9553L_VDDA: length 4.6
  TOP w0.254: C29.1 38.52,11.39 U11.14
  TOP w0.635: L1.1 40.87,9.91 40.87,10.84 40.31,11.4 C30.1 C29.1
P1V8_PED: length 25.6
  TOP w0.254: U11.1 37.12,13.7 37.31,13.89 38.13,13.89
  TOP w0.635: v1(38.66,15.6) 38.94,15.32 C25.1 C26.1 38.38,13.64 38.13,13.89 ; L1.2 v1(37.62,9.91)
  BOTTOM w0.635: v1(38.66,15.6) 38.66,10.95 v1(37.62,9.91) 38.23,9.3 38.23,7.54 37.64,6.96 30.39,6.96 J20.2
P3V3: length 207.4
  TOP w0.305: R35.1 42.65,18.34 41.91,17.6 C44.1 41.31,18.13 U6.5
  TOP w0.508: J11.P4 3.51,27.04
  TOP w0.635: v1(11.4,35.38) 12.47,36.45 R61.1 R62.1 ; R63.1 67.51,5.33 v1(66.75,6.1) ; R63.1 67.51,3.38 R64.1 67.56,2.24 66.52,1.19 36.91,1.19 J9.4 35.52,3.94 34.76,4.7 C41.1 C40.1 30.81,2.95 J9.2 29.57,3.46 29.57,4.22 J22.2 ; R63.1 67.56,4.88 68.53,4.88 68.83,4.57 68.83,3.73 69.58,2.98 73.11,2.98 74.7,4.57 Q2.1 ; v1(12.67,27.2) 11.56,27.2 C11.1 C13.1 3.64,27.18 3.51,27.04 ; R35.1 43.03,19.39 43.61,19.98 J13.2 ; J13.2 43.45,20.77 39.88,20.77 J14.2 39.63,20.84 38.73,20.84 36.76,22.81 29.16,22.81 28.79,22.44 26.96,22.44 v1(23.95,19.43) ; J13.2 43.91,20.63 44.79,20.63 45.42,21.27 45.42,22.7 46.19,23.47 J17.1
  BOTTOM w0.635: J12.2 56.2,20.64 57.04,20.64 57.82,21.43 57.82,22.63 58.59,23.39 J16.1 ; J16.1 61,23.39 61.55,22.85 61.55,19.48 62.97,18.06 63.98,18.06 66.67,15.37 66.67,9.25 66.12,8.69 66.12,6.73 v1(66.75,6.1) ; J16.1 59.79,25.31 59.59,25.52 59.59,34.05 61.66,36.12 J7.1 ; v1(11.4,35.38) 11.4,30.15 12.67,28.88 v1(12.67,27.2) 11.2,25.73 11.2,22.58 13.64,20.14 15.76,20.14 J15.2 18.18,19.43 v1(23.95,19.43) 23.95,17.44 26.91,14.48 27.41,14.48 28.37,13.51 28.37,12.58 J18.2 28.42,12.35 28.42,11.51 27.91,11 25.42,11 24.18,9.76 24.18,8.35 25.34,7.19 27.43,7.19 28.28,6.34 28.28,5.52 J22.2
P3V3_ACCEL: length 16.4
  TOP w0.178: C15.1 43.02,28.79 43.24,29.01 U3.8 ; U3.1 44.04,32.7 43.96,32.79 43.96,33.41 44.07,33.52 C4.1
  TOP w0.635: C4.1 44.6,33.13 v1(45.1,32.63) ; C15.1 43.03,28.12 v1(43.03,27.36)
  BOTTOM w0.635: v1(45.1,32.63) 45.1,29.43 v1(43.03,27.36) 43.03,26.56 43.61,25.98 J13.1
P3V3_BT: length 4.9
  TOP w0.635: J7.2 66.16,35.21 C1.1 66.16,33.88 C3.1 66.16,31.49 U5.9
P3V3_COMBO: length 38.7
  TOP w0.305: U9.14 v2(64.99,11.97) ; U9.1 v2(61.95,16.52)
  TOP w0.635: R55.1 57.52,7.67 R57.1 57.52,7.07 v1(57.91,6.68) ; v2(64.99,11.97) 64.99,11.06 C32.1 ; C20.1 C19.1 63.15,16.52 v2(61.95,16.52)
  BOTTOM w0.635: J16.2 59.79,19.09 58.85,18.15 58.85,16.17 59.35,15.67 61.39,15.67 61.95,16.23 v2(61.95,16.52) 63.36,16.52 63.88,16 63.88,12.32 64.24,11.97 v2(64.99,11.97) 64.99,8.17 63.5,6.68 v1(57.91,6.68)
P3V3_GYRO: length 24.2
  TOP w0.254: U4.15 21.92,28.54 v1(21.92,29.45) ; U4.18 20.42,29.18 20.12,29.48 v1(20.12,29.45)
  TOP w0.635: C9.1 22.15,29.68 v1(21.92,29.45) ; J15.1 16.78,23.7 17.78,23.7 18.59,22.89 18.61,22.89 18.64,22.85 R27.1 v1(19.52,21.84) ; R5.1 23.32,32.04 22.99,32.37 v1(22.7,32.37) 20.9,32.37 20.9,32.37 20.57,32.37 20.23,32.03 R4.1
  BOTTOM w0.635: v1(22.7,32.37) 22.7,30.23 v1(21.92,29.45) v1(20.12,29.45) 19.52,28.85 v1(19.52,21.84)
P3V3_MAG: length 21.7
  TOP w0.178: v1(55.4,33.74) 55.4,32.55 54.76,31.91 54.76,30.82 U2.2 ; v1(54.64,25.32) 54.64,26.7 54.36,26.97 U2.8
  TOP w0.635: C2.1 55.54,33.88 v1(55.4,33.74) ; J12.1 54.32,23.42 53.66,24.09 C16.1 v1(54.64,25.32)
  BOTTOM w0.635: v1(55.4,33.74) 55.4,32.69 56.29,31.8 56.29,26.98 v1(54.64,25.32)
P3V3_PEDOM: length 42.6
  TOP w0.305: 34.43,8.05 35.34,8.05 C36.1 36.33,7.44 36.62,7.73 U12.6
  TOP w0.432: 21.21,16.03 20.98,15.8 U8.8 ; U8.5 22.93,16.23 C21.1
  TOP w0.635: J18.1 24.54,13.69 24.54,15.44 23.75,16.23 C21.1 21.41,16.23 21.21,16.03 ; J18.1 25.74,11.28 26.38,10.64 29.82,10.64 31.17,9.3 33.18,9.3 34.43,8.05 ; J18.1 25.74,14.18 26.81,15.25 v1(26.81,15.95) 28.02,15.95 R43.1 28.04,16.56 C23.1 28.04,17.48 28.77,18.14 R36.1 ; v1(34.82,18.18) 33.81,18.18 R37.1
  BOTTOM w0.635: v1(26.81,15.95) 29.04,18.18 v1(34.82,18.18)
P3V3_PRESSURE: length 14.1
  TOP w0.635: v1(38.08,26.06) C14.1 38.15,27.14 38.18,27.17 C12.1 36.95,28.43 U1.1 ; U1.4 v1(38,32.18)
  BOTTOM w0.635: v1(38,32.18) 38,31.48 38.08,31.4 v1(38.08,26.06) 38.08,25.11 J14.1
P3V3_SPI_ACC: length 18.5
  TOP w0.305: U10.14 v2(49.64,11.81) ; U10.1 v2(46.6,16.36)
  TOP w0.635: C28.1 49.88,11.56 v2(49.64,11.81) ; J17.2 47.4,19.72 47.14,19.47 C22.1 47.14,16.9 v2(46.6,16.36)
  BOTTOM w0.635: v2(49.64,11.81) 48.89,11.81 48.36,12.33 48.36,14.6 v2(46.6,16.36)
P3V3_VBAT: length 4.8
  TOP w0.381: C38.1 23.08,7.42 23.08,7.42 U13.1
  TOP w0.635: J22.1 24.24,5.51 23.73,6.01 C38.1
P3V7_BAT: length 9
  TOP w0.432: R53.1 19.32,7.96 U13.8
  TOP w0.635: SW1.6 SW1.3 19.28,5.15 C37.1 18.91,6.55 18.37,7.09 18.37,7.82 R53.1
P4V2_BAT: length 17.2
  TOP w0.635: C35.1 SW1.2 SW1.5
  BOTTOM w0.635: SW1.5 15.65,2.72 11.46,2.72 J19.2 9.28,3.19 8.02,3.19 8.02,3.24 J24.2
P4V2_BAT_OUT: length 14.4
  TOP w0.254: 5.32,8.62 U14.8
  TOP w0.508: J19.1 8.43,8.28 5.66,8.28 5.32,8.62
  TOP w0.635: J19.1 12.6,6.58 SW1.1 SW1.4
P5V_USB: length 52.2
  TOP w0.254: C34.1 5.32,11.19 U14.1
  TOP w0.635: Q1.1 12.43,10.78 R56.1 10.79,9.4 R52.1 8.79,9.4 R54.1 7.19,9.37 v1(6.88,9.68) 6.88,10.01 6.27,10.62 C34.1 ; v1(37.08,4.42) C43.1 38.33,4.5 C42.1 39.75,4.47 39.75,3.76 39.49,3.5 38.98,3.5 J9.5
  BOTTOM w0.508: 36.8,1.93 36.8,3.3
  BOTTOM w0.635: 36.8,1.93 36.04,1.17 25.35,1.17 16.84,9.68 v1(6.88,9.68) ; 36.8,3.3 36.8,4.14 v1(37.08,4.42)
VBAT_EN: length 5.4
  TOP w0.127: U13.5 19.1,9.91 18.92,9.73 18.92,9.38 R53.2 18.31,9.38 17.55,10.13 Q1.3
ACC_BYP: length 5
  TOP w0.127: U10.2 v1(46.1,17.22) 46.1,17.78 C17.1
BAT_CHG_B: length 4.9
  TOP w0.127: U14.3 3.76,11.94 4.32,12.5 5.32,12.5 6.59,13.77 D2.C
BAT_CHG_EN: length 2.1
  TOP w0.127: R50.1 3.25,12.57 3.26,12.56 U14.4
BAT_CHG_LED_B: length 3.8
  TOP w0.127: R52.2 10.31,12.81 9.36,13.77 D2.A
BAT_ISET: length 1.7
  TOP w0.127: U14.7 4.26,7.73 R60.1
BAT_PPR_B: length 3.7
  TOP w0.127: D3.C 6.59,12.4 6.16,11.96 4.6,11.96 4.26,11.63 U14.2
BAT_PPR_LED_B: length 1.5
  TOP w0.127: D3.A 8.75,11.81 8.76,11.8 R54.2
BT_CTS: length 2.3
  TOP w0.127: R8.2 63.65,31.17 63.65,31.17 U5.11
BT_MONITOR: length 34.3
  TOP w0.127: v1(67.36,15.82) 66.88,16.31 R38.1 66.88,18.54 67.15,18.81 U5.23
  BOTTOM w0.127: J10.2 54.7,1.24 65.61,1.24 69.29,4.93 TP36.1 69.29,11.61 67.82,13.08 67.82,15.37 v1(67.36,15.82)
BT_RTS: length 4.6
  TOP w0.127: R8.1 62.13,30.18 62.63,29.68 U5.12
BT_RX: length 6.4
  TOP w0.127: J26.2 59.51,26.39 61.31,26.39 62.6,27.68 U5.14
BT_RX0: length 28.4
  TOP w0.127: TP8.1 63.53,39.26 64.14,38.64 64.14,35.06 63.6,34.52 62.16,34.52 60.86,33.22 60.86,33.22 59.59,31.95 59.59,27.9 59.91,27.58 J25.2
  BOTTOM w0.127: J1.1 62.26,49.61 62.26,41.94 TP8.1
BT_TX: length 3.4
  TOP w0.127: U5.13 62.76,28.68 61.31,30.12 J25.1
BT_TX0: length 22.9
  TOP w0.127: TP7.1 60.99,34.5 58.32,31.83 J26.1
  BOTTOM w0.127: TP7.1 59.72,41.94 59.72,49.61 J1.2
BT_WAKEUP: length 37.8
  TOP w0.127: U5.26 v1(70.15,18.67)
  BOTTOM w0.127: J10.1 52.47,0.94 66.55,0.94 70.37,4.76 70.37,12.38 TP37.1 71.04,17.77 v1(70.15,18.67)
BTMON_LED: length 1.4
  TOP w0.127: R38.2 D1.A
BYP_ACC: length 1.9
  TOP w0.127: U3.4 42.84,32.59 42.57,32.86 C5.1
BYP_FXOS8700CQ: length 4.8
  TOP w0.127: U9.2 v1(61.46,17.38) 61.46,18.5 C18.1
CAP_A_MAG: length 3.8
  TOP w0.127: C7.1 v1(56.17,32.92) 56.17,32.16 55.16,31.15 U2.1
CAP_MPL3115A2: length 1.3
  TOP w0.127: C10.1 37.68,29.68 37.68,29.68 U1.2
CAP_R_MAG: length 4.5
  TOP w0.127: C6.1 53.32,33.75 v1(54.22,33.75) 54.22,33.28 53.96,33.03 U2.4
CRST_FXOS8700CQ: length 3.7
  TOP w0.127: C31.1 56.46,11.51 v1(56.92,11.97) U9.8
EN_MMA9553L: length 3.9
  TOP w0.127: R43.2 29.56,16.1 30.03,16.57 U7.8 30.93,15.77 31.06,15.63 31.29,15.63 31.43,15.77 U7.7
FACTORY_RSVD: length 2.9
  TOP w0.127: TP25.1 72.82,18.21 72.15,18.88 U5.28
I2C_SCL0: length 83.4
  TOP w0.127: v1(27,21.04) 27.03,21.06 R29.2 ; R11.2 48.19,27.12 v1(48.63,27.55) 48.9,27.82 R12.2 ; TP9.1 18.87,39.13 19,39 R61.2 ; v1(24.64,26.29) 25.22,25.7 R25.2 25.35,25.45 26.04,26.14 27.38,26.14 27.69,26.44 32.61,26.44 33.22,27.05 35.08,27.05 35.71,26.42 R24.2 36.35,26.29 37.47,25.17 45.62,25.17 45.82,25.37 v1(46.26,25.37) 48.21,25.37 49.81,23.76 49.81,20.14 51.41,18.54 R34.2
  BOTTOM w0.127: v1(46.26,25.37) 46.26,25.81 48,27.55 v1(48.63,27.55) ; J2.10 20.14,49.56 20.14,41.94 TP9.1 22.2,37.34 24.57,37.34 25.05,36.86 25.05,26.7 v1(24.64,26.29) 25.15,25.78 25.15,22.89 v1(27,21.04)
I2C_SCL1: length 77.6
  TOP w0.127: R64.2 65.24,3.33 64.49,2.58 J10.6 ; R33.2 v1(54.05,17.09) 51.54,17.09 49.41,19.22 49.41,23.49 v1(48.07,24.83) 36.36,24.83 36.35,24.82 R23.2 35.71,24.69 35,23.98 33.55,23.98 32.08,25.45 v1(27.97,25.45) R26.2 ; R30.2 30.12,21.67 v1(29.82,21.97) ; R7.2 R6.2 47.57,30.96 47.27,31.27 TP20.1
  BOTTOM w0.127: v1(48.07,24.83) 48.07,26.33 49.09,27.35 49.09,30.53 TP20.1 ; v1(54.05,17.09) 55.52,15.62 55.52,7.37 55.17,7.01 55.17,4.67 55.96,3.89 62.22,3.89 J10.6 ; v1(27.97,25.45) 27.97,23.83 v1(29.82,21.97)
I2C_SCL_FXAS21000CQ: length 6.3
  TOP w0.127: R26.1 R25.1 25.1,23.93 24.18,24.84 24.18,26.93 23.9,27.21 U4.11
I2C_SCL_FXOS8700CQ: length 9.2
  TOP w0.127: R34.1 R33.1 58.34,17.09 58.63,17.38 v1(60.45,17.38) U9.4
I2C_SCL_MAG3110: length 9.3
  TOP w0.127: R7.1 50.42,30.2 R12.1 50.42,28.18 v1(50.89,27.71) ; U2.7 53.96,26.51 53.95,26.51 v1(53.95,25.75)
  BOTTOM w0.127: v1(50.89,27.71) 52.17,26.43 53.15,26.43 53.83,25.75 v1(53.95,25.75)
I2C_SCL_MMA8652FC: length 11.6
  TOP w0.127: U3.2 43.64,33.56 44.38,34.3 45.95,34.3 46.5,33.75 46.5,33.31 46.05,32.86 R6.1 46.05,30.07 46.5,29.62 46.5,28.94 46.8,28.64 R11.1
I2C_SCL_MMA9553_LV: length 6.1
  TOP w0.127: U11.4 35.64,13.28 35.64,13.79 35.43,14 34.95,14 34.72,14.22 R40.2 33.96,14.86 33.66,14.55 32.11,14.55 31.93,14.37 U7.3
I2C_SCL_MMA9553L: length 5.9
  TOP w0.127: R29.1 R30.1 30.5,19.54 30.81,19.23 R36.2 30.81,18.01 31.26,17.56 31.64,17.56 31.93,17.27 U7.6
I2C_SCL_MPL3115A2: length 5.8
  TOP w0.127: v1(33.27,26.29) R24.1 R23.1 ; v1(33.68,28.43) U1.8
  BOTTOM w0.127: v1(33.68,28.43) 33.68,26.7 v1(33.27,26.29)
I2C_SDA0: length 79.1
  TOP w0.127: TP10.1 21.41,39.12 20.9,38.61 R62.2 ; R16.2 27.51,26.95 28.01,27.45 29.2,27.45 v1(29.51,27.76) 29.98,28.22 R14.2 31,28.1 31.69,27.41 35.99,27.41 37.87,25.53 45.01,25.53 45.76,26.28 R20.2 46.48,26.4 46.95,25.93 48.58,25.93 49.35,25.16 R19.2 49.99,24.36 v1(50.61,23.73) ; R39.2 v1(53.75,15.63) ; v1(30.89,21.88) 30.89,21.3 31.12,21.08 R32.2
  BOTTOM w0.127: J2.9 22.68,49.56 22.68,41.94 TP10.1 22.61,40.67 25.57,37.71 25.57,35.14 27.18,33.53 29.36,33.53 29.84,33.05 29.84,28.09 v1(29.51,27.76) 29.16,27.41 29.16,23.62 v1(30.89,21.88) ; v1(53.75,15.63) 50.61,18.77 v1(50.61,23.73)
I2C_SDA1: length 92.5
  TOP w0.127: R18.2 49.35,26.63 v1(48.99,26.37) 47.18,26.37 45.76,27.8 R21.2 ; R31.2 33.32,21.92 v1(33.3,21.95) ; R13.2 28.3,28.42 29.56,29.68 R10.2 30.99,30.48 v1(31.22,30.71) 31.22,31.95 32.74,33.48 37.36,33.48 37.67,33.17 40.36,33.17 42.02,34.83 48.38,34.83 TP19.1 ; R63.2 65.05,4.83 64.47,4.24 61.49,4.24 60.99,3.74 J10.5 ; R48.2 v1(53.81,14.16)
  BOTTOM w0.127: v1(31.22,30.71) 31.22,24.03 v1(33.3,21.95) ; J10.5 59.99,1.57 55.32,1.57 54.64,2.26 54.64,3.2 54.25,3.58 54.25,8.89 54.89,9.52 54.89,13.08 v1(53.81,14.16) 49.56,18.41 49.56,23.59 48.99,24.15 v1(48.99,26.37) 49.67,27.05 49.67,30.86 50.22,31.41 TP19.1
I2C_SDA_FXAS21000CQ: length 3.9
  TOP w0.127: R16.1 R13.1 24.69,28.42 23.97,27.71 U4.12
I2C_SDA_FXOS8700CQ: length 5.6
  TOP w0.127: U9.6 v1(56.93,12.99) 56.92,13.56 56.44,14.04 R48.1 56.44,14.17 R39.1
I2C_SDA_MAG3110: length 6.1
  TOP w0.127: R18.1 R19.1 52.29,25.16 v1(52.94,25.8) 52.94,27.36 53.56,27.98 U2.6
I2C_SDA_MMA8652FC: length 3.6
  TOP w0.127: R20.1 R21.1 44.23,28.74 44.04,28.93 U3.10
I2C_SDA_MMA9553_LV: length 4
  TOP w0.127: U7.4 32.88,13.57 33.08,13.37 R49.2 33.12,11.91 33.71,11.91 34.19,12.39 U11.6
I2C_SDA_MMA9553L: length 4.7
  TOP w0.127: R31.1 33.27,19.56 R32.1 31.88,18.69 32.28,18.29 R37.2 32.28,17.48 32.43,17.33 U7.5
I2C_SDA_MPL3115A2: length 3.7
  TOP w0.127: R14.1 32.52,28.23 32.52,29.67 R10.1 34.05,29.68 U1.7
I2CSEL_FXAS21000CQ: length 2.5
  TOP w0.127: R4.2 20.04,30.51 20.92,29.63 U4.17
INT1_ACC: length 5.6
  TOP w0.127: R68.2 46.08,6.53 45.6,7 v1(45.6,8.25) U10.11
INT1_ACCEL: length 7.3
  TOP w0.127: U3.3 43.24,33.92 v1(43.41,34.09)
  BOTTOM w0.127: v1(43.41,34.09) 43.88,34.56 46.31,34.56 46.9,35.15 J4.3
INT1_COMBO: length 35.3
  TOP w0.127: v1(64.01,8.43) R66.2
  BOTTOM w0.127: v1(64.01,8.43) 64.01,9.19 51.24,21.97 51.24,24.94 50.28,25.9 50.28,30.16 51.55,31.43 51.55,34 50.7,34.85 J3.1
INT1_COMBO_R: length 5.8
  TOP w0.127: R66.1 62.18,7.32 61.77,6.91 61.19,6.91 60.95,7.14 v1(60.95,8.41) U9.11
INT1_GYRO: length 15.4
  TOP w0.127: v1(20.45,23.62) 20.92,24.09 U4.3
  BOTTOM w0.127: J6.1 23.98,27.15 v1(20.45,23.62)
INT1_PRESSURE: length 8.1
  TOP w0.127: U1.6 v1(33.62,30.93)
  BOTTOM w0.127: J5.3 33.62,31.73 v1(33.62,30.93)
INT1_SPI_ACCEL: length 42.4
  TOP w0.127: R68.1 48.51,6.55 v1(48.51,7.57)
  BOTTOM w0.127: v1(48.51,7.57) 47.62,6.68 43.92,6.68 42.52,8.08 42.52,15.32 32.56,25.27 32.56,25.91 31.83,26.64 31.83,34.77 30.53,36.07 J6.3
INT2_ACC: length 7.6
  TOP w0.127: U10.9 44.6,8.85 44.48,8.72 v1(44.48,8.28) 44.48,6.7 46.18,5 R67.2
INT2_ACCEL: length 1.9
  TOP w0.127: U3.5 42.12,31.77 TP33.1
INT2_COMBO: length 33.9
  TOP w0.127: R65.2 v1(54.15,10.74)
  BOTTOM w0.127: v1(54.15,10.74) 54.15,12.9 48.74,18.31 47.98,18.31 47.02,19.27 43.65,19.27 41.82,21.11 J4.1
INT2_COMBO_R: length 7.9
  TOP w0.127: U9.9 v1(59.95,8.41) 59.15,9.22 R65.1
INT2_GYRO: length 5.6
  TOP w0.127: TP32.1 16.94,25.53 18.47,24 20.2,24 20.42,24.22 U4.2
INT2_PRESSURE: length 2
  TOP w0.127: U1.5 33.62,32.18 33.62,32.18 TP34.1
INT2_SPI_ACCEL: length 1.5
  TOP w0.127: TP31.1 R67.1
INT_ACCEL: length 22.1
  TOP w0.127: TP4.1 50.22,37.57 45.82,37.57 J4.2
  BOTTOM w0.127: J1.5 52.1,49.61 52.1,41.94 TP4.1
INT_GYRO: length 39.2
  TOP w0.127: TP3.1 48.34,38.23 41.91,38.23 37.72,34.04 28.55,34.04 J6.2
  BOTTOM w0.127: J1.6 49.53,49.58 49.53,42.01 TP3.1
INT_MAG: length 19.3
  BOTTOM w0.127: J3.2 55.24,38.1 57.53,38.1 58.45,39.01 TP6.1 57.18,41.94 57.18,49.61 J1.3
INT_MAG3110: length 16.1
  TOP w0.127: U2.9 54.76,27.98 54.76,27.28 55.6,26.44 v1(55.6,25.02)
  BOTTOM w0.127: J3.3 57.08,34.79 57.08,26.49 v1(55.6,25.02)
INT_MMA9553L_LV: length 1.2
  TOP w0.127: U11.11 36.12,9.78 36.12,9.77 U12.2
INT_PED: length 19.7
  TOP w0.127: J5.2 37.3,37.95 39.01,37.95 TP17.1
  BOTTOM w0.127: J2.1 43.33,49.23 43.33,42.27 TP17.1
INT_PEDOMETER: length 40.1
  TOP w0.127: v1(34.95,8.84) 35.23,8.56 35.6,8.56 U12.4
  BOTTOM w0.127: J5.1 31.42,37.52 28.8,37.52 27.91,36.63 27.91,35.64 30.76,32.79 30.76,27.89 30.18,27.3 30.18,23.77 32.83,21.12 34.84,21.12 36.14,19.81 36.14,18.29 34.95,17.09 v1(34.95,8.84)
